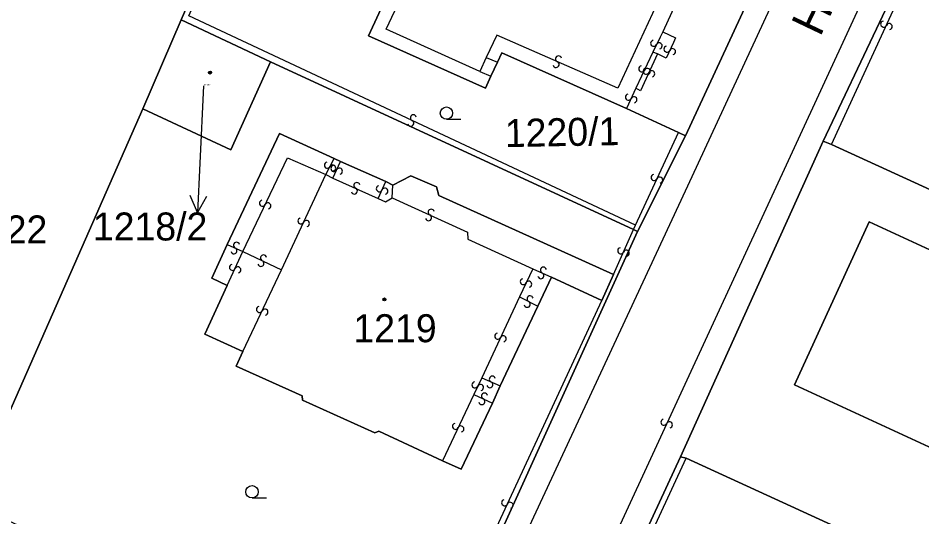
# Model space of a CAD drawing. Extents: x -600309 to -598967, y -1161267 to -1160292.
# Drawn here: x -600137.8 to -600082.9, y -1160470.9 to -1160440.6 of the extents above; entities that cross this region are included whole.
import ezdxf

# ---------------------------------------------------------------- set-up
doc = ezdxf.new("R2010")
doc.units = 0
for name, color, linetype in [('Level 1', 7, 'Continuous'), ('Level 11', 7, 'Continuous'), ('Level 13', 7, 'Continuous'), ('Level 3', 7, 'Continuous'), ('Level 4', 7, 'Continuous'), ('Level 5', 7, 'Continuous'), ('Level 57', 7, 'Continuous'), ('Level 60', 7, 'Continuous')]:
    doc.layers.add(name, color=color, linetype=linetype)

msp = doc.modelspace()

# ---------------------------------------------------------------- linework, layer by layer
at = {"layer": 'Level 1'}
for points in [[(-600088.87, -1160448.11), (-600082.04, -1160433.68)], [(-600127.87, -1160440.75), (-600125.06, -1160434.3)], [(-600091.32, -1160435.02), (-600097.24, -1160447.8)], [(-600115.23, -1160438.98), (-600116.48, -1160441.71), (-600109.38, -1160444.89), (-600109.06, -1160444.16)], [(-600130.2, -1160446.15), (-600127.87, -1160440.75)], [(-600127.87, -1160440.75), (-600122.44, -1160443.3)], [(-600108.65, -1160443.32), (-600108.38, -1160442.75), (-600100.82, -1160446.14)], [(-600130.2, -1160446.15), (-600124.84, -1160448.64), (-600122.44, -1160443.3)], [(-600122.44, -1160443.3), (-600100.4, -1160453.49)], [(-600109.06, -1160444.16), (-600108.65, -1160443.32)], [(-600140.73, -1160470.09), (-600130.2, -1160446.15)], [(-600100.82, -1160446.14), (-600097.65, -1160447.58)], [(-600125.06, -1160454.4), (-600121.9, -1160447.66), (-600118.57, -1160449.17)], [(-600097.65, -1160447.58), (-600097.24, -1160447.8)], [(-600097.24, -1160447.8), (-600100.14, -1160453.61)], [(-600097.53, -1160467.3), (-600088.87, -1160448.11)], [(-600088.36, -1160448.32), (-600088.87, -1160448.11)], [(-600061, -1160460.85), (-600088.36, -1160448.32)], [(-600118.57, -1160449.17), (-600118.18, -1160449.35)], [(-600118.18, -1160449.35), (-600115.44, -1160450.57)], [(-600115.01, -1160450.79), (-600113.92, -1160450.22), (-600112.36, -1160450.9), (-600112.22, -1160451.41), (-600101.6, -1160456.21)], [(-600115.44, -1160450.57), (-600115.01, -1160450.79)], [(-600074.56, -1160470.33), (-600070.03, -1160460.43), (-600086.08, -1160453.01), (-600090.62, -1160462.91), (-600074.56, -1160470.33)], [(-600100.14, -1160453.61), (-600113.39, -1160482.74)], [(-600100.4, -1160453.49), (-600100.14, -1160453.61)], [(-600125.06, -1160456.89), (-600126.01, -1160456.44), (-600125.06, -1160454.4)], [(-600105.37, -1160456.38), (-600106.21, -1160458.14)], [(-600102.31, -1160457.79), (-600105.37, -1160456.38)], [(-600101.6, -1160456.21), (-600102.31, -1160457.79)], [(-600124.12, -1160460.9), (-600126.43, -1160459.85), (-600125.06, -1160456.89)], [(-600106.21, -1160458.14), (-600108.48, -1160462.98)], [(-600112, -1160467.53), (-600115.86, -1160465.73), (-600116.1, -1160465.84), (-600120.49, -1160463.85), (-600120.51, -1160463.59), (-600124.52, -1160461.79), (-600124.12, -1160460.9)], [(-600108.48, -1160462.98), (-600108.96, -1160464.03)], [(-600108.96, -1160464.03), (-600110.86, -1160468.05), (-600112, -1160467.53)], [(-600106.35, -1160486.3), (-600097.53, -1160467.3)], [(-600097.2, -1160467.38), (-600097.53, -1160467.3)], [(-600069.78, -1160479.95), (-600097.2, -1160467.38)]]:
    msp.add_lwpolyline(points, dxfattribs=at)
at = {"layer": 'Level 13'}
for centre, start, end in [((-600085.197, -1160441.002), 102.7206, 334.8186), ((-600084.863, -1160441.158), 282.5061, 155.0961), ((-600099.166, -1160442.171), 101.8663, 334.4563), ((-600098.834, -1160442.33), 282.0807, 154.1787), ((-600098.357, -1160442.523), 102.8053, 335.3953), ((-600098.023, -1160442.678), 283.0197, 155.1177), ((-600105.095, -1160443.458), 193.7434, 65.8414), ((-600104.945, -1160443.122), 13.5289, 246.1189), ((-600099.886, -1160443.721), 101.8686, 334.4586), ((-600099.617, -1160443.862), 102.2535, 334.8435), ((-600099.554, -1160443.88), 282.0831, 154.1811), ((-600099.283, -1160444.019), 282.468, 154.566), ((-600100.697, -1160445.442), 102.267, 334.857), ((-600100.363, -1160445.599), 282.4814, 154.5794), ((-600113.761, -1160446.694), 12.0397, 244.6297), ((-600113.92, -1160447.026), 192.2541, 64.3521), ((-600118.984, -1160449.575), 100.3419, 332.4399), ((-600118.656, -1160449.744), 280.1274, 152.7174), ((-600118.586, -1160449.781), 102.418, 334.516), ((-600118.253, -1160449.938), 282.2035, 154.7935), ((-600099.136, -1160450.321), 102.3725, 334.4705), ((-600098.804, -1160450.479), 282.1581, 154.7481), ((-600117.346, -1160451.148), 192.9651, 65.5551), ((-600117.193, -1160450.812), 13.1795, 245.2775), ((-600115.828, -1160451.005), 103.7725, 335.8705), ((-600115.492, -1160451.154), 283.5581, 156.1481), ((-600122.926, -1160451.889), 101.9445, 334.0425), ((-600122.594, -1160452.05), 281.7301, 154.3201), ((-600112.837, -1160452.767), 192.5822, 65.1722), ((-600112.682, -1160452.433), 12.7967, 244.8947), ((-600120.586, -1160452.961), 102.4156, 334.5136), ((-600120.253, -1160453.118), 282.2011, 154.7911), ((-600124.504, -1160454.442), 13.5223, 245.6203), ((-600124.655, -1160454.778), 193.3078, 65.8978), ((-600101.168, -1160454.774), 103.5668, 335.6648), ((-600100.832, -1160454.925), 283.3523, 155.9423), ((-600123.019, -1160455.546), 191.875, 64.465), ((-600122.86, -1160455.214), 12.0895, 244.1875), ((-600124.747, -1160455.782), 102.7206, 334.8186), ((-600124.413, -1160455.938), 282.5061, 155.0961), ((-600105.863, -1160455.952), 13.2705, 245.3685), ((-600107.086, -1160456.65), 101.8121, 334.4021), ((-600106.016, -1160456.288), 193.056, 65.646), ((-600106.754, -1160456.81), 282.0266, 154.1246), ((-600106.675, -1160457.696), 10.6016, 242.6996), ((-600123.106, -1160458.339), 101.9721, 334.0701), ((-600106.844, -1160458.024), 190.3871, 62.9771), ((-600122.774, -1160458.5), 281.7576, 154.3476), ((-600108.637, -1160459.962), 102.1988, 334.7888), ((-600108.304, -1160460.119), 282.4132, 154.5112), ((-600108.966, -1160462.571), 14.358, 246.456), ((-600110.016, -1160462.92), 101.5173, 334.1073), ((-600109.684, -1160463.081), 281.7317, 153.8297), ((-600109.113, -1160462.909), 194.1435, 66.7335), ((-600109.44, -1160463.604), 12.2449, 244.3429), ((-600109.599, -1160463.936), 192.0305, 64.6205), ((-600111.206, -1160465.44), 101.7999, 334.3899), ((-600098.547, -1160465.192), 102.3738, 334.9638), ((-600098.213, -1160465.349), 282.5883, 154.6863), ((-600110.874, -1160465.601), 282.0143, 154.1123), ((-600108.217, -1160470.081), 102.4891, 334.5871), ((-600107.883, -1160470.238), 282.2746, 154.8646)]:
    msp.add_arc(centre, 0.184, start, end, dxfattribs=at)
at = {"layer": 'Level 3'}
for points in [[(-600125.19, -1160509.33), (-600124.47, -1160508.8), (-600123.86, -1160508.11), (-600109.68, -1160477.91), (-600096.82, -1160450.26), (-600074.94, -1160403), (-600061.88, -1160376.37), (-600052.36, -1160359.27)], [(-600048.26, -1160362.83), (-600048.91, -1160363.35), (-600049.47, -1160364), (-600049.93, -1160364.77), (-600057.69, -1160378.67), (-600063.2, -1160389.22), (-600076.75, -1160418.43), (-600120.01, -1160512.12), (-600120.19, -1160512.54)], [(-600109.72, -1160443.88), (-600115.42, -1160441.31), (-600111.94, -1160433.92)], [(-600088.36, -1160448.32), (-600081.71, -1160433.83)], [(-600100.28, -1160453.22), (-600127.39, -1160440.51), (-600124.75, -1160434.45)], [(-600098.44, -1160438.63), (-600101.34, -1160444.9), (-600108.7, -1160441.68), (-600109.34, -1160443.04)], [(-600097.52, -1160439.06), (-600098.61, -1160441.47)], [(-600098.61, -1160441.47), (-600098.78, -1160441.8), (-600099.21, -1160442.71)], [(-600098.61, -1160441.47), (-600097.85, -1160441.84), (-600097.97, -1160442.13), (-600098.4, -1160443.08), (-600098.93, -1160442.82)], [(-600099.21, -1160442.71), (-600100.24, -1160444.89)], [(-600098.93, -1160442.82), (-600099.21, -1160442.71)], [(-600109.34, -1160443.04), (-600109.72, -1160443.88)], [(-600109.34, -1160443.04), (-600108.65, -1160443.32)], [(-600098.93, -1160442.82), (-600099.97, -1160445.06), (-600100.24, -1160444.89)], [(-600109.72, -1160443.88), (-600109.06, -1160444.16)], [(-600100.24, -1160444.89), (-600100.82, -1160446.14)], [(-600100.28, -1160453.22), (-600097.65, -1160447.58)], [(-600124.11, -1160454.82), (-600121.4, -1160449.12), (-600119.07, -1160450.15)], [(-600119.07, -1160450.15), (-600118.57, -1160449.17)], [(-600118.65, -1160450.36), (-600118.18, -1160449.35)], [(-600121.76, -1160455.93), (-600119.07, -1160450.15)], [(-600119.07, -1160450.15), (-600118.65, -1160450.36)], [(-600118.65, -1160450.36), (-600115.89, -1160451.6)], [(-600115.89, -1160451.6), (-600115.44, -1160450.57)], [(-600115.05, -1160451.56), (-600115.01, -1160450.79)], [(-600115.89, -1160451.6), (-600115.46, -1160451.81), (-600115.05, -1160451.56)], [(-600115.05, -1160451.56), (-600110.48, -1160453.65), (-600110.46, -1160454.07), (-600106.51, -1160455.87)], [(-600100.4, -1160453.49), (-600100.28, -1160453.22)], [(-600101.6, -1160456.21), (-600100.4, -1160453.49)], [(-600125.06, -1160454.4), (-600124.11, -1160454.82)], [(-600125.06, -1160456.89), (-600124.11, -1160454.82)], [(-600124.11, -1160454.82), (-600121.76, -1160455.93)], [(-600124.12, -1160460.9), (-600121.76, -1160455.93)], [(-600106.51, -1160455.87), (-600107.32, -1160457.58)], [(-600106.51, -1160455.87), (-600105.37, -1160456.38)], [(-600107.32, -1160457.58), (-600109.61, -1160462.5)], [(-600107.32, -1160457.58), (-600106.21, -1160458.14)], [(-600113.79, -1160482.54), (-600102.31, -1160457.79)], [(-600109.61, -1160462.5), (-600110.09, -1160463.5)], [(-600109.61, -1160462.5), (-600108.48, -1160462.98)], [(-600110.09, -1160463.5), (-600112, -1160467.53)], [(-600110.09, -1160463.5), (-600108.96, -1160464.03)], [(-600106.02, -1160486.46), (-600097.2, -1160467.38)]]:
    msp.add_lwpolyline(points, dxfattribs=at)
at = {"layer": 'Level 5'}
for p, q in [((-600111.75, -1160446.79), (-600110.875, -1160446.79)), ((-600123.56, -1160469.79), (-600122.685, -1160469.79))]:
    msp.add_line(p, q, dxfattribs=at)
for centre, radius in [((-600126.11, -1160443.95), 0.09), ((-600126.11, -1160443.95), 0.0521), ((-600111.75, -1160446.415), 0.375), ((-600115.52, -1160457.73), 0.09), ((-600115.52, -1160457.73), 0.0521), ((-600123.56, -1160469.415), 0.375)]:
    msp.add_circle(centre, radius, dxfattribs=at)
at = {"layer": 'Level 57'}
for p, q in [((-600126.51, -1160444.75), (-600126.73, -1160449.453)), ((-600126.73, -1160449.453), (-600126.87, -1160452.45))]:
    msp.add_line(p, q, dxfattribs=at)
msp.add_lwpolyline([(-600126.324, -1160451.474), (-600126.87, -1160452.45), (-600127.323, -1160451.427)], dxfattribs=at)
at = {"layer": 'Level 60'}
for points in [[(-600062.24, -1160391.06), (-600071.2, -1160410.1), (-600072.61, -1160413.33), (-600077.89, -1160424.81), (-600079.93, -1160429.23), (-600081.08, -1160431.67), (-600082.04, -1160433.68), (-600088.87, -1160448.11), (-600097.53, -1160467.3), (-600106.35, -1160486.3), (-600110.04, -1160494.24), (-600112.36, -1160499.24), (-600118.46, -1160512.51)], [(-600120.19, -1160512.54), (-600125.19, -1160509.33), (-600128.67, -1160507.09), (-600124.35, -1160505.9), (-600118.57, -1160493.73), (-600117.89, -1160492.25), (-600115.6, -1160487.34), (-600113.39, -1160482.74), (-600100.14, -1160453.61), (-600097.24, -1160447.8), (-600091.32, -1160435.02), (-600089.16, -1160430.27), (-600079.56, -1160409.29), (-600076.23, -1160402.09)]]:
    msp.add_lwpolyline(points, dxfattribs=at)
for points in [[(-600150.18, -1160491.39), (-600150.37, -1160491.77), (-600154.65, -1160488.46), (-600159.23, -1160484.79), (-600159.11, -1160484.51), (-600156, -1160478.17), (-600149.97, -1160480.76), (-600149.15, -1160481.16), (-600147.98, -1160481.65), (-600142.41, -1160469), (-600150.31, -1160465.42), (-600149.15, -1160462.67), (-600127.7, -1160412.49), (-600117.59, -1160417.16), (-600125.06, -1160434.3), (-600127.87, -1160440.75), (-600130.2, -1160446.15), (-600140.73, -1160470.09)], [(-600091.75, -1160434.82), (-600091.32, -1160435.02), (-600097.24, -1160447.8), (-600097.65, -1160447.58), (-600100.82, -1160446.14), (-600108.38, -1160442.75), (-600108.65, -1160443.32), (-600109.06, -1160444.16), (-600109.38, -1160444.89), (-600116.48, -1160441.71), (-600115.23, -1160438.98), (-600112.73, -1160433.5), (-600112.38, -1160432.88), (-600111.46, -1160430.81), (-600111.36, -1160430.63), (-600114.06, -1160429.38), (-600112.2, -1160425.49), (-600109.5, -1160426.72), (-600109.03, -1160425.67), (-600105.61, -1160427.25), (-600099.17, -1160430.08), (-600099.72, -1160431.19)], [(-600052.37, -1160441.93), (-600061, -1160460.85), (-600088.36, -1160448.32), (-600088.87, -1160448.11), (-600082.04, -1160433.68), (-600081.71, -1160433.83), (-600078.36, -1160435.36), (-600079.34, -1160437.41), (-600078.33, -1160437.86), (-600082.19, -1160445.92), (-600065.24, -1160453.69), (-600063.03, -1160449.09), (-600065.45, -1160447.91), (-600062.96, -1160442.48), (-600069.32, -1160439.54), (-600068.34, -1160437.6), (-600071.26, -1160436.18), (-600080.8, -1160431.8), (-600081.08, -1160431.67), (-600079.93, -1160429.23), (-600079.59, -1160429.26)], [(-600122.44, -1160443.3), (-600127.87, -1160440.75), (-600125.06, -1160434.3), (-600124.75, -1160434.45), (-600115.23, -1160438.98), (-600116.48, -1160441.71), (-600109.38, -1160444.89), (-600109.06, -1160444.16), (-600108.65, -1160443.32), (-600108.38, -1160442.75), (-600100.82, -1160446.14), (-600097.65, -1160447.58), (-600097.24, -1160447.8), (-600100.14, -1160453.61), (-600100.4, -1160453.49)], [(-600130.2, -1160446.15), (-600127.87, -1160440.75), (-600122.44, -1160443.3), (-600124.84, -1160448.64)], [(-600113.79, -1160482.54), (-600140.73, -1160470.09), (-600130.2, -1160446.15), (-600124.84, -1160448.64), (-600122.44, -1160443.3), (-600100.4, -1160453.49), (-600100.14, -1160453.61), (-600113.39, -1160482.74)], [(-600101.6, -1160456.21), (-600102.31, -1160457.79), (-600105.37, -1160456.38), (-600106.21, -1160458.14), (-600108.48, -1160462.98), (-600108.96, -1160464.03), (-600110.86, -1160468.05), (-600112, -1160467.53), (-600115.86, -1160465.73), (-600116.1, -1160465.84), (-600120.49, -1160463.85), (-600120.51, -1160463.59), (-600124.52, -1160461.79), (-600124.12, -1160460.9), (-600126.43, -1160459.85), (-600125.06, -1160456.89), (-600126.01, -1160456.44), (-600125.06, -1160454.4), (-600121.9, -1160447.66), (-600118.57, -1160449.17), (-600118.18, -1160449.35), (-600115.44, -1160450.57), (-600115.01, -1160450.79), (-600113.92, -1160450.22), (-600112.36, -1160450.9), (-600112.22, -1160451.41)], [(-600102.31, -1160457.79), (-600101.6, -1160456.21), (-600112.22, -1160451.41), (-600112.36, -1160450.9), (-600113.92, -1160450.22), (-600115.01, -1160450.79), (-600115.44, -1160450.57), (-600118.18, -1160449.35), (-600118.57, -1160449.17), (-600121.9, -1160447.66), (-600125.06, -1160454.4), (-600126.01, -1160456.44), (-600125.06, -1160456.89), (-600126.43, -1160459.85), (-600124.12, -1160460.9), (-600124.52, -1160461.79), (-600120.51, -1160463.59), (-600120.49, -1160463.85), (-600116.1, -1160465.84), (-600115.86, -1160465.73), (-600112, -1160467.53), (-600110.86, -1160468.05), (-600108.96, -1160464.03), (-600108.48, -1160462.98), (-600106.21, -1160458.14), (-600105.37, -1160456.38)], [(-600088.36, -1160448.32), (-600061, -1160460.85), (-600050.57, -1160465.66), (-600059.3, -1160484.66), (-600069.78, -1160479.95), (-600097.2, -1160467.38), (-600097.53, -1160467.3), (-600088.87, -1160448.11)], [(-600070.03, -1160460.43), (-600074.56, -1160470.33), (-600090.62, -1160462.91), (-600086.08, -1160453.01)], [(-600074.56, -1160470.33), (-600070.03, -1160460.43), (-600086.08, -1160453.01), (-600090.62, -1160462.91)], [(-600097.2, -1160467.38), (-600069.78, -1160479.95), (-600078.52, -1160499.04), (-600087.98, -1160494.7), (-600106.02, -1160486.46), (-600106.35, -1160486.3), (-600097.53, -1160467.3)]]:
    msp.add_lwpolyline(points, close=True, dxfattribs=at)

# ---------------------------------------------------------------- texts
at = {"layer": 'Level 11'}
msp.add_text('Hlávkova', height=2, rotation=64.4909, dxfattribs=at).set_placement((-600089.062, -1160441.83))
at = {"layer": 'Level 4'}
for s, height, p in [('1218/2', 0.1, (-600126.51, -1160444.75)), ('1222', 1.7, (-600141.05, -1160454.33)), ('1219', 1.7, (-600117.403, -1160460.33))]:
    msp.add_text(s, height=height, dxfattribs=at).set_placement(p)
msp.add_text('1220/1', height=1.7, rotation=1.0408, dxfattribs=at).set_placement((-600108.19, -1160448.48))
at = {"layer": 'Level 57'}
msp.add_text('1218/2', height=1.7, dxfattribs=at).set_placement((-600133.224, -1160454.15))

doc.saveas('drawing.dxf')
